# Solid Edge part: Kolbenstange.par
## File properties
Username: ahadarics
Dokumentum tartalom típus: 0
Author: ahadarics
Last saved by: ahadarics
Revision: 85
Sűrűség: 0,000 kg/m^3
Pontosság: 0,990
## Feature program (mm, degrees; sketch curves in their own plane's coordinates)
base feature "unnamed BaseFeature 1"
sketch for "unnamed Protrusion 1" plane through (59.95, 0, 0) normal (1, 0, 0) x-axis (0, -1, 0)
  circle centre (0, 0) radius 10
extrude "unnamed Protrusion 1" add finite 32 along -normal
thread "Menet_1"  ThreadDepth = 20 mm
chamfer "Letörés_1" setback 0.7
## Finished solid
Body 1: solid body, 13 faces, 23 edges, 12 vertices.
  Faces by surface: plane 9, cylinder 3, cone 1
  Edges by curve: line 12, circle 11
Bounding box of the edges (mm): 293.500 x 20.000 x 20.000, from (-233.55, -10, -10) to (59.95, 10, 10).
Cylindrical faces by radius (mm): R4 x2, R10 x1
Conical faces (half-angle, radius in mm at the cone's reference point): 45 deg R3.3 x1
Planar faces by outward normal: +x 3, +z 1, -x 4, -z 1
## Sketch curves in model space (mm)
circle centre (59.95, 0, 0) radius 10
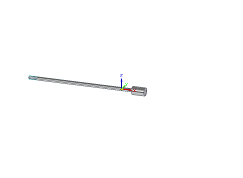
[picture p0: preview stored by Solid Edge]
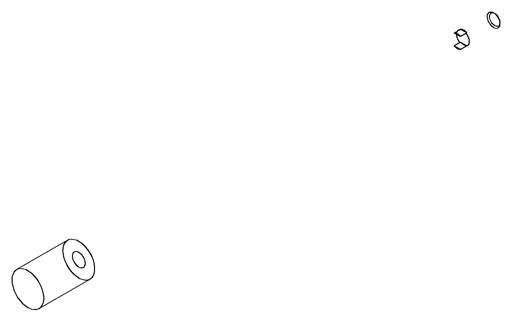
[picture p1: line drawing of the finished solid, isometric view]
